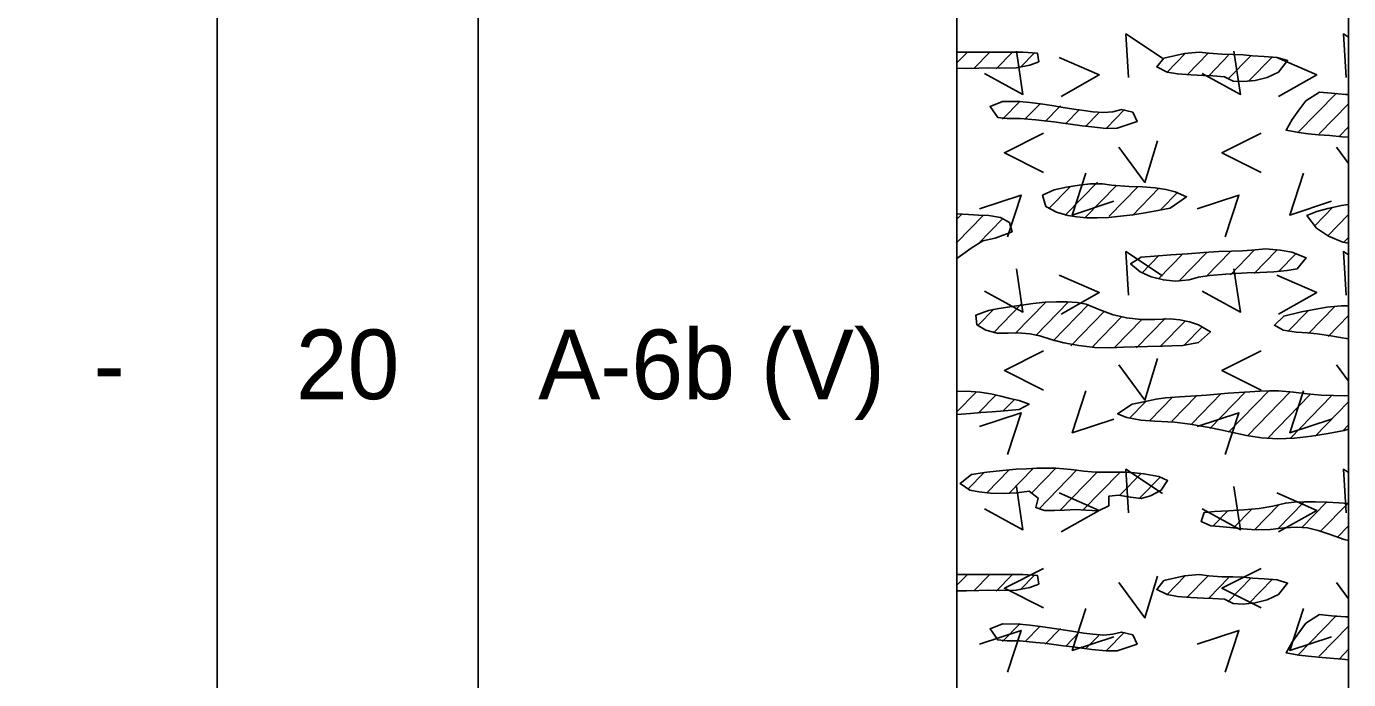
# Model space of a CAD drawing. Extents: x -0.01 to 0.83, y -0.63 to 1.27.
# Drawn here: x 0.7067 to 0.8333, y 0.9385 to 1.001 of the extents above; entities that cross this region are included whole.
import ezdxf

# ---------------------------------------------------------------- set-up
doc = ezdxf.new("R2010")
doc.units = 0

msp = doc.modelspace()

# ---------------------------------------------------------------- linework, layer by layer
for points in [[(0, 0), (0.83333, 0), (0.83333, 1.275), (0, 1.275)], [(0, 0), (0.83333, 0), (0.83333, 1.275), (0, 1.275)], [(0, 0), (0.83333, 0), (0.83333, 1.275), (0, 1.275)], [(0, 0), (0.83333, 0), (0.83333, 1.275), (0, 1.275)], [(0, 0), (0.83333, 0), (0.83333, 1.275), (0, 1.275)], [(0.79583, 0.99696), (0.79676, 0.99695), (0.79792, 0.99697), (0.79882, 0.99701), (0.79992, 0.99697), (0.80151, 0.99701), (0.80282, 0.99727), (0.80367, 0.99759), (0.80354, 0.99842), (0.80216, 0.99851), (0.79583, 0.99851)], [(0.81822, 0.99632), (0.81944, 0.99626), (0.82033, 0.99622), (0.82145, 0.99615), (0.82229, 0.99573), (0.82324, 0.99569), (0.82438, 0.9958), (0.82555, 0.99608), (0.82662, 0.99659), (0.82749, 0.99769), (0.82651, 0.99799), (0.82524, 0.99809), (0.82413, 0.99815), (0.82324, 0.99826), (0.82226, 0.99828), (0.82121, 0.9983), (0.81995, 0.99839), (0.81902, 0.99851), (0.81761, 0.99837), (0.81566, 0.99793), (0.81496, 0.99709), (0.81598, 0.9966), (0.81695, 0.99642)], [(0.80066, 0.99216), (0.80188, 0.99215), (0.80339, 0.99202), (0.80423, 0.99193), (0.8051, 0.99182), (0.806, 0.9917), (0.80692, 0.99158), (0.80784, 0.99146), (0.80875, 0.99135), (0.81014, 0.99121), (0.81119, 0.99122), (0.81222, 0.99157), (0.81308, 0.99185), (0.81267, 0.99275), (0.8116, 0.993), (0.81075, 0.9928), (0.80989, 0.99272), (0.80885, 0.9928), (0.80799, 0.99291), (0.80703, 0.99305), (0.806, 0.99322), (0.80492, 0.99339), (0.80384, 0.99354), (0.8028, 0.99367), (0.80182, 0.99377), (0.8002, 0.99377), (0.79901, 0.9933), (0.79974, 0.99226)], [(0.83305, 0.99446), (0.83171, 0.99457), (0.83054, 0.99467), (0.82925, 0.99385), (0.82857, 0.99294), (0.82792, 0.99205), (0.82735, 0.99103), (0.82858, 0.9908), (0.82945, 0.9907), (0.83045, 0.9906), (0.83155, 0.99051), (0.83272, 0.99041), (0.83333, 0.99036), (0.83333, 0.99445)], [(0.81233, 0.98565), (0.81063, 0.98577), (0.80977, 0.98591), (0.8086, 0.98591), (0.80755, 0.98577), (0.80632, 0.98557), (0.80513, 0.98533), (0.80403, 0.9848), (0.80436, 0.98374), (0.80536, 0.98318), (0.80647, 0.98288), (0.8073, 0.98273), (0.80824, 0.98265), (0.80926, 0.98264), (0.81035, 0.98269), (0.81149, 0.9828), (0.81267, 0.98294), (0.81386, 0.98313), (0.81506, 0.98334), (0.81625, 0.98357), (0.81783, 0.98466), (0.81673, 0.98515), (0.81585, 0.98536), (0.8148, 0.98551), (0.81361, 0.98562)], [(0.83265, 0.98384), (0.83136, 0.98353), (0.83028, 0.98326), (0.82934, 0.98286), (0.83026, 0.98166), (0.83142, 0.9809), (0.83279, 0.98032), (0.83333, 0.98022), (0.83333, 0.98393)], [(0.79583, 0.97874), (0.79719, 0.97973), (0.79831, 0.98044), (0.79951, 0.98071), (0.80111, 0.98131), (0.80086, 0.98219), (0.80002, 0.98267), (0.79889, 0.98286), (0.79791, 0.98289), (0.79694, 0.98295), (0.79583, 0.98303)], [(0.82537, 0.97969), (0.82408, 0.97954), (0.82319, 0.97948), (0.82214, 0.97946), (0.82091, 0.97942), (0.81947, 0.97933), (0.81792, 0.97921), (0.81632, 0.97909), (0.81475, 0.97899), (0.81348, 0.97889), (0.81247, 0.97825), (0.81337, 0.97749), (0.81444, 0.97699), (0.81561, 0.9767), (0.81675, 0.9766), (0.81807, 0.97671), (0.81896, 0.97698), (0.82003, 0.97713), (0.82157, 0.97725), (0.82253, 0.97731), (0.82362, 0.97737), (0.82483, 0.97743), (0.82618, 0.97749), (0.82745, 0.9776), (0.82842, 0.97778), (0.82927, 0.97883), (0.82791, 0.97935), (0.82679, 0.97955)], [(0.79885, 0.97378), (0.79763, 0.97332), (0.79773, 0.97242), (0.79859, 0.9719), (0.7997, 0.9716), (0.80074, 0.97161), (0.80165, 0.97163), (0.80281, 0.97154), (0.80377, 0.97134), (0.80486, 0.97099), (0.80606, 0.97069), (0.80751, 0.97042), (0.80905, 0.97023), (0.81052, 0.9702), (0.81177, 0.97026), (0.81289, 0.9703), (0.81408, 0.97033), (0.81553, 0.97037), (0.81642, 0.9704), (0.81745, 0.97043), (0.81897, 0.9707), (0.82011, 0.97174), (0.81896, 0.97241), (0.8181, 0.97268), (0.81717, 0.97287), (0.81626, 0.97298), (0.81479, 0.97292), (0.81343, 0.97292), (0.8121, 0.97307), (0.8108, 0.97337), (0.80953, 0.97383), (0.8082, 0.97438), (0.80736, 0.97454), (0.8064, 0.97462), (0.80536, 0.97462), (0.80427, 0.97456), (0.80314, 0.97445), (0.80201, 0.9743), (0.8009, 0.97414), (0.79984, 0.97396)], [(0.83263, 0.97422), (0.83126, 0.97409), (0.82969, 0.97382), (0.82883, 0.97365), (0.82712, 0.97324), (0.82623, 0.97237), (0.82708, 0.97188), (0.82831, 0.97169), (0.82941, 0.97163), (0.83033, 0.97154), (0.83165, 0.97135), (0.83253, 0.97121), (0.83333, 0.97107), (0.83333, 0.97422)], [(0.79583, 0.96382), (0.79715, 0.96393), (0.79814, 0.96401), (0.79922, 0.96408), (0.80039, 0.96417), (0.80179, 0.96429), (0.80275, 0.9648), (0.80179, 0.96515), (0.80091, 0.96536), (0.80003, 0.96558), (0.79909, 0.96579), (0.79803, 0.96595), (0.79677, 0.96605), (0.79583, 0.96603)], [(0.82816, 0.96157), (0.82978, 0.96174), (0.83137, 0.962), (0.8329, 0.96231), (0.83333, 0.96241), (0.83333, 0.96565), (0.83295, 0.96562), (0.83188, 0.96564), (0.83071, 0.96569), (0.82938, 0.9658), (0.82807, 0.96596), (0.82662, 0.96608), (0.82576, 0.96609), (0.82484, 0.96606), (0.82387, 0.96601), (0.82286, 0.96594), (0.82182, 0.96586), (0.82077, 0.96578), (0.81973, 0.96569), (0.81872, 0.96562), (0.81715, 0.96552), (0.81579, 0.96543), (0.81491, 0.9653), (0.81357, 0.96502), (0.8126, 0.96481), (0.81121, 0.96389), (0.8121, 0.96353), (0.81345, 0.96328), (0.81479, 0.96319), (0.81668, 0.96309), (0.81818, 0.96289), (0.81905, 0.96274), (0.82, 0.96257), (0.82107, 0.96235), (0.82225, 0.9621), (0.82357, 0.96181), (0.82501, 0.96158), (0.82656, 0.96151)], [(0.79708, 0.95659), (0.79794, 0.95641), (0.79904, 0.9563), (0.80028, 0.95627), (0.80156, 0.95632), (0.80274, 0.95648), (0.80361, 0.95582), (0.80338, 0.95492), (0.80422, 0.95465), (0.80517, 0.95463), (0.80613, 0.95468), (0.8072, 0.95472), (0.80818, 0.95468), (0.80939, 0.95461), (0.81037, 0.95508), (0.81038, 0.95602), (0.8113, 0.95609), (0.81244, 0.9559), (0.81346, 0.95579), (0.81438, 0.95605), (0.81539, 0.95659), (0.81601, 0.9575), (0.81517, 0.95788), (0.81374, 0.95815), (0.81285, 0.95825), (0.81187, 0.9583), (0.81, 0.95831), (0.8091, 0.95832), (0.808, 0.9584), (0.80678, 0.95856), (0.8053, 0.95869), (0.80443, 0.9587), (0.80349, 0.95868), (0.80251, 0.95864), (0.80152, 0.95858), (0.80054, 0.9585), (0.79959, 0.95841), (0.7987, 0.95831), (0.79722, 0.95809), (0.79614, 0.95721)], [(0.83241, 0.95537), (0.83129, 0.95544), (0.83017, 0.95547), (0.8291, 0.95548), (0.82811, 0.95544), (0.82728, 0.95535), (0.82608, 0.95505), (0.82476, 0.95482), (0.8233, 0.95469), (0.82183, 0.95461), (0.82051, 0.95455), (0.81951, 0.95445), (0.81922, 0.95358), (0.82013, 0.95316), (0.82097, 0.95311), (0.822, 0.95301), (0.82318, 0.95288), (0.82448, 0.95279), (0.82584, 0.95282), (0.82719, 0.95298), (0.82836, 0.95305), (0.8294, 0.95297), (0.83043, 0.95274), (0.83156, 0.95235), (0.83291, 0.95186), (0.83333, 0.95178), (0.83333, 0.9553)], [(0.79583, 0.94696), (0.79676, 0.94695), (0.79792, 0.94697), (0.79882, 0.94701), (0.79992, 0.94697), (0.80151, 0.94701), (0.80282, 0.94727), (0.80367, 0.94759), (0.80354, 0.94842), (0.80216, 0.94851), (0.79583, 0.94851)], [(0.81822, 0.94632), (0.81944, 0.94626), (0.82033, 0.94622), (0.82145, 0.94615), (0.82229, 0.94573), (0.82324, 0.94569), (0.82438, 0.9458), (0.82555, 0.94608), (0.82662, 0.94659), (0.82749, 0.94769), (0.82651, 0.94799), (0.82524, 0.94809), (0.82413, 0.94815), (0.82324, 0.94826), (0.82226, 0.94828), (0.82121, 0.9483), (0.81995, 0.94839), (0.81902, 0.94851), (0.81761, 0.94837), (0.81566, 0.94793), (0.81496, 0.94709), (0.81598, 0.9466), (0.81695, 0.94642)], [(0.83305, 0.94446), (0.83171, 0.94457), (0.83054, 0.94467), (0.82925, 0.94385), (0.82857, 0.94294), (0.82792, 0.94205), (0.82735, 0.94103), (0.82858, 0.9408), (0.82945, 0.9407), (0.83045, 0.9406), (0.83155, 0.94051), (0.83272, 0.94041), (0.83333, 0.94036), (0.83333, 0.94445)], [(0.80066, 0.94216), (0.80188, 0.94215), (0.80339, 0.94202), (0.80423, 0.94193), (0.8051, 0.94182), (0.806, 0.9417), (0.80692, 0.94158), (0.80784, 0.94146), (0.80875, 0.94135), (0.81014, 0.94121), (0.81119, 0.94122), (0.81222, 0.94157), (0.81308, 0.94185), (0.81267, 0.94275), (0.8116, 0.943), (0.81075, 0.9428), (0.80989, 0.94272), (0.80885, 0.9428), (0.80799, 0.94291), (0.80703, 0.94305), (0.806, 0.94322), (0.80492, 0.94339), (0.80384, 0.94354), (0.8028, 0.94367), (0.80182, 0.94377), (0.8002, 0.94378), (0.79901, 0.9433), (0.79974, 0.94226)]]:
    msp.add_lwpolyline(points, close=True)
for points in [[(0.725, 1.22083), (0.725, -0.62183)], [(0.75, 1.22083), (0.75, -0.62183)], [(0.75, 1.22083), (0.75, -0.62183)], [(0.79583, 1.22083), (0.79583, -0.62183)], [(0.725, 1.20833), (0.725, -0.62183)], [(0.83333, -0.62183), (0.83333, 1.13843)], [(0.81551, 0.99794), (0.81201, 1.00025), (0.81226, 0.99607)], [(0.83333, 0.99993), (0.83284, 1.00025), (0.83309, 0.99607)], [(0.79583, 0.99748), (0.79681, 0.99848)], [(0.79898, 0.9985), (0.79747, 0.99695)], [(0.79847, 0.99646), (0.80215, 0.99446), (0.80153, 0.99858)], [(0.80116, 0.99851), (0.79959, 0.99691)], [(0.80328, 0.99847), (0.80188, 0.99704)], [(0.80562, 0.998), (0.80946, 0.99632), (0.80581, 0.99426)], [(0.8177, 0.99837), (0.81596, 0.99659)], [(0.81988, 0.99839), (0.81785, 0.99631)], [(0.8193, 0.99646), (0.82299, 0.99446), (0.82236, 0.99858)], [(0.82185, 0.9982), (0.81997, 0.99627)], [(0.824, 0.99819), (0.82178, 0.99591)], [(0.82601, 0.99803), (0.82378, 0.99575)], [(0.82645, 0.998), (0.83029, 0.99632), (0.82664, 0.99426)], [(0.80188, 0.99381), (0.8002, 0.99209)], [(0.83217, 0.99459), (0.82844, 0.99077)], [(0.8038, 0.99357), (0.80237, 0.99211)], [(0.80575, 0.99335), (0.80429, 0.99186)], [(0.80758, 0.99302), (0.80627, 0.99167)], [(0.80941, 0.99269), (0.80816, 0.9914)], [(0.81188, 0.993), (0.81016, 0.99124)], [(0.83333, 0.99357), (0.83052, 0.99069)], [(0.83333, 0.99136), (0.83245, 0.99045)], [(0.80412, 0.99075), (0.80038, 0.98887), (0.80412, 0.987)], [(0.81134, 0.98941), (0.81384, 0.98603), (0.81503, 0.99003)], [(0.82496, 0.99075), (0.82121, 0.98887), (0.82496, 0.987)], [(0.83217, 0.98941), (0.83333, 0.98784)], [(0.80818, 0.98691), (0.80687, 0.98291), (0.81087, 0.98423)], [(0.82901, 0.98691), (0.8277, 0.98291), (0.8317, 0.98423)], [(0.80069, 0.98083), (0.802, 0.98483), (0.798, 0.98352)], [(0.80465, 0.98354), (0.80667, 0.98561)], [(0.80626, 0.98297), (0.80928, 0.98607)], [(0.80809, 0.98264), (0.81111, 0.98573)], [(0.81041, 0.9828), (0.81318, 0.98563)], [(0.81264, 0.98288), (0.81518, 0.98548)], [(0.81536, 0.98345), (0.81699, 0.98511)], [(0.82152, 0.98083), (0.82284, 0.98483), (0.81884, 0.98352)], [(0.8301, 0.98187), (0.83184, 0.98366)], [(0.7963, 0.98299), (0.79583, 0.98251)], [(0.79834, 0.98286), (0.79583, 0.98029)], [(0.79786, 0.98016), (0.80023, 0.98259)], [(0.83131, 0.9809), (0.83333, 0.98298)], [(0.83285, 0.98027), (0.83333, 0.98076)], [(0.81551, 0.97711), (0.81201, 0.97942), (0.81226, 0.97523)], [(0.81519, 0.97906), (0.81354, 0.97736)], [(0.81514, 0.9768), (0.81748, 0.97919)], [(0.81709, 0.97658), (0.81974, 0.9793)], [(0.8197, 0.97703), (0.82203, 0.97943)], [(0.82202, 0.9772), (0.8243, 0.97954)], [(0.82431, 0.97733), (0.82644, 0.97952)], [(0.82663, 0.9775), (0.82834, 0.97925)], [(0.83333, 0.9791), (0.83284, 0.97942), (0.83309, 0.97523)], [(0.79847, 0.97563), (0.80215, 0.97363), (0.80153, 0.97775)], [(0.8193, 0.97563), (0.82299, 0.97363), (0.82236, 0.97775)], [(0.80562, 0.97717), (0.80946, 0.97549), (0.80581, 0.97343)], [(0.82645, 0.97717), (0.83029, 0.97549), (0.82664, 0.97343)], [(0.79938, 0.97391), (0.79786, 0.97236)], [(0.79933, 0.97165), (0.80195, 0.97434)], [(0.80142, 0.97158), (0.8043, 0.97453)], [(0.80653, 0.97461), (0.8034, 0.97139)], [(0.80506, 0.97089), (0.8084, 0.97431)], [(0.80997, 0.97371), (0.80675, 0.9704)], [(0.82751, 0.97176), (0.82945, 0.97375)], [(0.83203, 0.97417), (0.82949, 0.97157)], [(0.81164, 0.9732), (0.80884, 0.97034)], [(0.81353, 0.97293), (0.81094, 0.97027)], [(0.81303, 0.97021), (0.81579, 0.97303)], [(0.81534, 0.97036), (0.81768, 0.97276)], [(0.8176, 0.97047), (0.81934, 0.97225)], [(0.83138, 0.9713), (0.83333, 0.9733)], [(0.83333, 0.97108), (0.83333, 0.97109)], [(0.80412, 0.96991), (0.80038, 0.96804), (0.80412, 0.96616)], [(0.82496, 0.96991), (0.82121, 0.96804), (0.82496, 0.96616)], [(0.81134, 0.96857), (0.81384, 0.9652), (0.81503, 0.9692)], [(0.83217, 0.96857), (0.83333, 0.96701)], [(0.79765, 0.96594), (0.79583, 0.96407)], [(0.80818, 0.96608), (0.80687, 0.96208), (0.81087, 0.96339)], [(0.81829, 0.96291), (0.82114, 0.96584)], [(0.82004, 0.96249), (0.82346, 0.966)], [(0.82569, 0.96608), (0.82184, 0.96213)], [(0.82775, 0.96598), (0.8237, 0.96183)], [(0.82901, 0.96608), (0.8277, 0.96208), (0.8317, 0.96339)], [(0.7996, 0.96572), (0.79786, 0.96394)], [(0.8013, 0.96524), (0.80027, 0.96419)], [(0.81392, 0.96508), (0.81235, 0.96348)], [(0.8143, 0.96326), (0.8165, 0.96551)], [(0.8164, 0.96319), (0.81879, 0.96564)], [(0.82964, 0.9657), (0.82557, 0.96152)], [(0.83173, 0.96563), (0.82774, 0.96154)], [(0.83333, 0.96505), (0.83012, 0.96176)], [(0.80069, 0.96), (0.802, 0.964), (0.798, 0.96269)], [(0.82152, 0.96), (0.82284, 0.964), (0.81884, 0.96269)], [(0.83281, 0.96231), (0.83333, 0.96284)], [(0.79844, 0.95828), (0.79691, 0.95671)], [(0.79871, 0.95634), (0.80085, 0.95853)], [(0.80083, 0.95629), (0.80311, 0.95863)], [(0.80534, 0.95871), (0.80299, 0.95629)], [(0.80367, 0.95478), (0.80732, 0.95852)], [(0.80571, 0.95466), (0.80924, 0.95828)], [(0.81142, 0.95829), (0.80785, 0.95464)], [(0.81551, 0.95627), (0.81201, 0.95859), (0.81226, 0.9544)], [(0.83333, 0.95827), (0.83284, 0.95859), (0.83309, 0.9544)], [(0.81141, 0.95607), (0.81348, 0.95819)], [(0.81528, 0.95783), (0.81331, 0.95581)], [(0.79847, 0.95479), (0.80215, 0.95279), (0.80153, 0.95692)], [(0.80562, 0.95634), (0.80946, 0.95465), (0.80581, 0.95259)], [(0.8193, 0.95479), (0.82299, 0.95279), (0.82236, 0.95692)], [(0.82645, 0.95634), (0.83029, 0.95465), (0.82664, 0.95259)], [(0.82035, 0.95315), (0.82176, 0.9546)], [(0.82233, 0.95298), (0.82408, 0.95476)], [(0.82433, 0.9528), (0.82666, 0.95519)], [(0.82909, 0.95548), (0.82656, 0.95288)], [(0.82885, 0.95301), (0.83122, 0.95544)], [(0.83325, 0.95531), (0.83065, 0.95265)], [(0.83333, 0.95318), (0.83227, 0.95209)], [(0.79583, 0.94748), (0.79681, 0.94848)], [(0.79898, 0.9485), (0.79747, 0.94695)], [(0.80116, 0.94851), (0.79959, 0.94691)], [(0.80412, 0.94908), (0.80038, 0.9472), (0.80412, 0.94533)], [(0.80328, 0.94847), (0.80188, 0.94704)], [(0.81134, 0.94774), (0.81384, 0.94436), (0.81503, 0.94836)], [(0.8177, 0.94837), (0.81596, 0.94659)], [(0.81988, 0.94839), (0.81785, 0.94631)], [(0.82185, 0.9482), (0.81997, 0.94627)], [(0.82496, 0.94908), (0.82121, 0.9472), (0.82496, 0.94533)], [(0.824, 0.94819), (0.82178, 0.94591)], [(0.82601, 0.94803), (0.82378, 0.94575)], [(0.83217, 0.94774), (0.83333, 0.94618)], [(0.80818, 0.94525), (0.80687, 0.94125), (0.81087, 0.94256)], [(0.82901, 0.94525), (0.8277, 0.94125), (0.8317, 0.94256)], [(0.83217, 0.94459), (0.82844, 0.94077)], [(0.80069, 0.93917), (0.802, 0.94317), (0.798, 0.94186)], [(0.80188, 0.94381), (0.8002, 0.94209)], [(0.8038, 0.94357), (0.80237, 0.94211)], [(0.80575, 0.94335), (0.80429, 0.94186)], [(0.82152, 0.93917), (0.82284, 0.94317), (0.81884, 0.94186)], [(0.83333, 0.94357), (0.83052, 0.94069)], [(0.80758, 0.94302), (0.80627, 0.94167)], [(0.80941, 0.94269), (0.80816, 0.9414)], [(0.81188, 0.943), (0.81016, 0.94124)], [(0.83333, 0.94136), (0.83245, 0.94045)]]:
    msp.add_lwpolyline(points)

# ---------------------------------------------------------------- texts
for s, height, p in [('A-6b (V)', 0.006667, (0.75575, 0.96529)), ('20', 0.006667, (0.73254, 0.96529)), ('-', 0.00667, (0.71318, 0.96529))]:
    msp.add_text(s, height=height).set_placement(p)

doc.saveas('drawing.dxf')
